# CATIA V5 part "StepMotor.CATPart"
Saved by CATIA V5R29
Part number: StepMotor
Revision: 훨부
Definition: 灌列
Nomenclature: C-35STM01_203
Source: Unknown
Bounding box of the stored display mesh (mm): x -24 to 25, y -48.6 to 17.6, z -17.6 to 17.6
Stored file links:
  C:\가치같이\SmartFactory_BoxErectorConveyor\Boxing(over)\StepMotor.CATPart
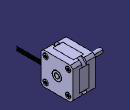
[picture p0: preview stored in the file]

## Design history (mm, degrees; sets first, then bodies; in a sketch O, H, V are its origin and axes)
Body1 "Cut-Extrude5" (main body)
  Solid1: solid without history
